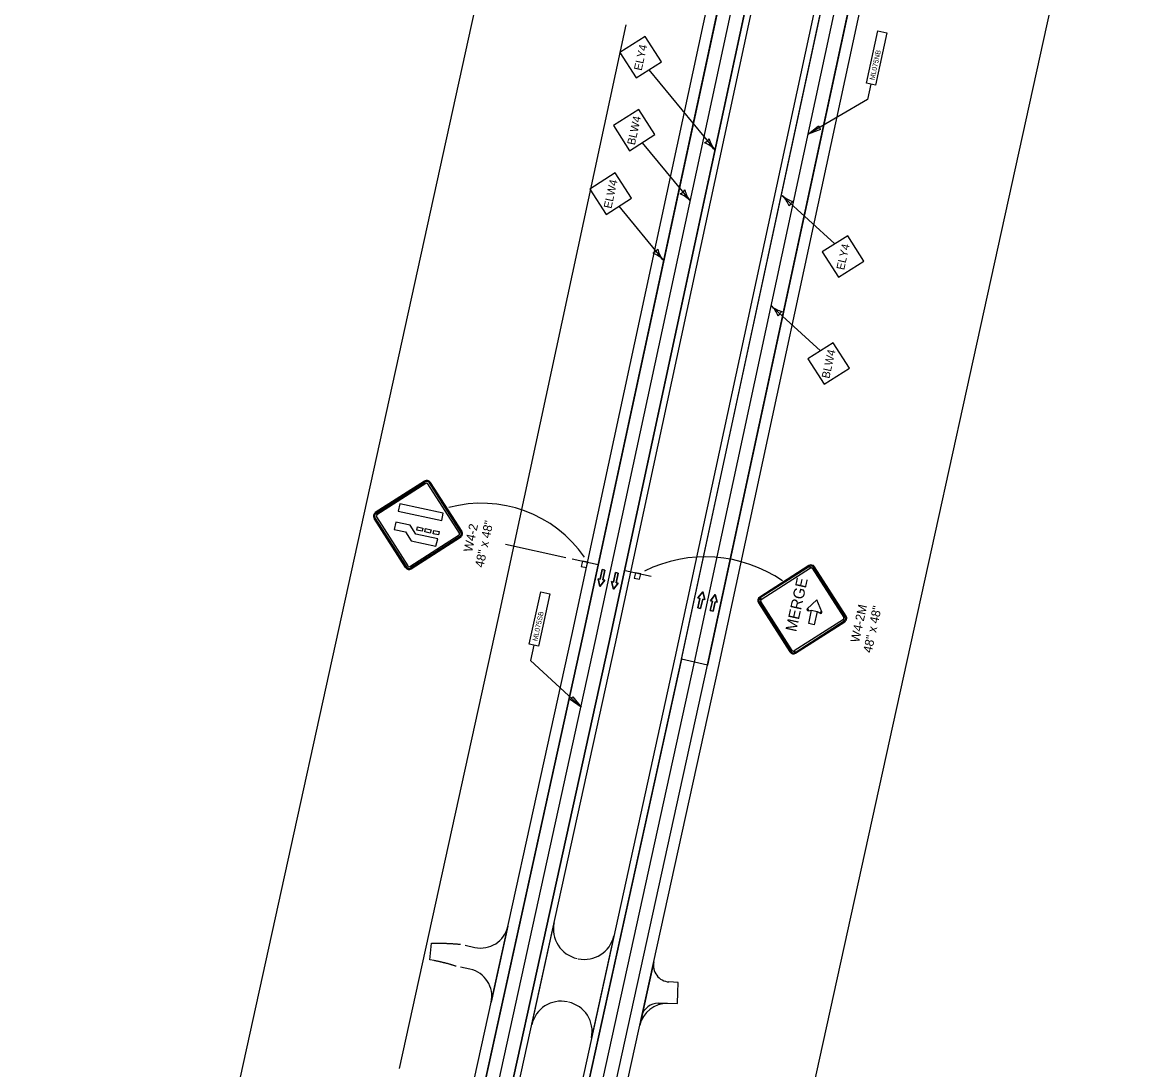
# Model space of a CAD drawing. Extents: x 14104283 to 14120882, y 8635219 to 8671666.
# Drawn here: x 14108108 to 14109111, y 8642822 to 8643764 of the extents above; entities that cross this region are included whole.
import ezdxf

# ---------------------------------------------------------------- set-up
doc = ezdxf.new("R2010")
doc.units = 0
for name, color, linetype in [('Cell', 7, 'Continuous'), ('dsnNonPlotable', 7, 'Continuous'), ('dsnPaintExistingEdgeLineRightWhite', 7, 'Continuous'), ('dsnPaintPlaceBrokenLineWhite', 7, 'Continuous'), ('dsnPaintPlaceEdgeLineLeftYellow', 7, 'Continuous'), ('dsnPaintPlaceEdgeLineRightWhite', 7, 'Continuous'), ('dsnPaintRemoveDoubleCenterLineYellow', 7, 'Continuous'), ('dsnShadingPaved', 7, 'Continuous'), ('dsnStdLabel', 7, 'Continuous'), ('dsnStgShadingPrevPav', 7, 'Continuous'), ('Text', 7, 'Continuous')]:
    doc.layers.add(name, color=color, linetype=linetype)

msp = doc.modelspace()

# ---------------------------------------------------------------- linework, layer by layer
at = {"layer": 'Cell'}
for p, q in [((14108425.2, 8643322.8), (14108469.5, 8643351.1)), ((14108469.5, 8643351.1), (14108425.2, 8643322.8)), ((14108425.7, 8643322), (14108470, 8643350.3)), ((14108470.8, 8643349), (14108426.6, 8643320.7)), ((14108500.8, 8643304.4), (14108472.5, 8643348.6)), ((14108473.9, 8643349.5), (14108502.1, 8643305.2)), ((14108474.6, 8643350), (14108502.9, 8643305.8)), ((14108502.9, 8643305.8), (14108474.6, 8643350)), ((14108452.4, 8643273.4), (14108424.1, 8643317.6)), ((14108424.1, 8643317.6), (14108452.4, 8643273.4)), ((14108424.1, 8643317.6), (14108424.1, 8643317.6)), ((14108453.2, 8643273.9), (14108424.9, 8643318.1)), ((14108426.2, 8643319), (14108426.2, 8643319)), ((14108426.2, 8643319), (14108454.5, 8643274.8)), ((14108456.2, 8643274.4), (14108500.5, 8643302.7)), ((14108501.3, 8643301.4), (14108457.1, 8643273.1)), ((14108501.8, 8643300.6), (14108457.6, 8643272.3)), ((14108457.6, 8643272.3), (14108501.8, 8643300.6)), ((14108602.2, 8643281.2), (14108625.7, 8643276.1)), ((14108815.1, 8643275.2), (14108770.9, 8643246.9)), ((14108815.6, 8643274.4), (14108816.5, 8643273.1)), ((14108818.2, 8643272.7), (14108819.5, 8643273.5)), ((14108848.6, 8643229.8), (14108820.3, 8643274)), ((14108649.9, 8643270.7), (14108673.3, 8643265.6)), ((14108770.5, 8643242.2), (14108771.9, 8643243)), ((14108772.2, 8643244.8), (14108771.4, 8643246.1)), ((14108769.7, 8643241.7), (14108798, 8643197.5)), ((14108814.4, 8643235.6), (14108813.7, 8643236.4)), ((14108814.5, 8643234.6), (14108814.4, 8643235.6)), ((14108825.7, 8643233.2), (14108825.2, 8643232.3)), ((14108826.7, 8643233.5), (14108825.7, 8643233.2)), ((14108803.2, 8643196.3), (14108847.4, 8643224.6)), ((14108846.1, 8643226.7), (14108846.9, 8643225.4)), ((14108847.8, 8643229.3), (14108846.5, 8643228.5)), ((14108800.1, 8643198.8), (14108798.8, 8643198)), ((14108802.7, 8643197.1), (14108801.9, 8643198.4))]:
    msp.add_line(p, q, dxfattribs=at)
for points in [[(14108470, 8643350.3), (14108425.7, 8643322)], [(14108470.8, 8643349), (14108426.6, 8643320.7)], [(14108500.8, 8643304.4), (14108472.5, 8643348.6)], [(14108502.1, 8643305.2), (14108473.9, 8643349.5)], [(14108424.9, 8643318.1), (14108453.2, 8643273.9)], [(14108426.2, 8643319), (14108454.5, 8643274.8)], [(14108456.2, 8643274.4), (14108500.5, 8643302.7)], [(14108457.1, 8643273.1), (14108501.3, 8643301.4)], [(14108616.2, 8643278.1), (14108611.4, 8643279.1), (14108610.4, 8643274.3), (14108615.2, 8643273.3), (14108616.2, 8643278.1)], [(14108627.3, 8643262.9), (14108625.5, 8643263.3), (14108627.2, 8643256.5), (14108631.6, 8643262), (14108629.8, 8643262.4), (14108631.6, 8643270.9), (14108629.2, 8643271.5), (14108627.3, 8643262.9)], [(14108639.4, 8643260.3), (14108637.6, 8643260.7), (14108639.3, 8643253.9), (14108643.7, 8643259.3), (14108641.8, 8643259.7), (14108643.7, 8643268.3), (14108641.3, 8643268.8), (14108639.4, 8643260.3)], [(14108663.9, 8643267.6), (14108659.1, 8643268.6), (14108658.1, 8643263.8), (14108662.9, 8643262.8), (14108663.9, 8643267.6)], [(14108719.6, 8643245.1), (14108721.5, 8643244.7), (14108719.7, 8643251.5), (14108715.4, 8643246.1), (14108717.2, 8643245.7), (14108715.3, 8643237.1), (14108717.8, 8643236.6), (14108719.6, 8643245.1)], [(14108719.6, 8643245.1), (14108721.5, 8643244.7), (14108719.7, 8643251.5), (14108715.4, 8643246.1), (14108717.2, 8643245.7), (14108715.3, 8643237.1), (14108717.8, 8643236.6), (14108719.6, 8643245.1)], [(14108730.7, 8643242.7), (14108732.6, 8643242.3), (14108730.8, 8643249.1), (14108726.5, 8643243.6), (14108728.3, 8643243.2), (14108726.4, 8643234.7), (14108728.9, 8643234.1), (14108730.7, 8643242.7)]]:
    msp.add_lwpolyline(points, dxfattribs=at)
for points in [[(14108445.8, 8643324.2), (14108484.9, 8643315.6), (14108486.3, 8643322.2), (14108447.2, 8643330.8)], [(14108452.5, 8643305.4), (14108457.5, 8643297.5), (14108479.8, 8643292.6), (14108481.3, 8643299.2), (14108461.7, 8643303.5), (14108456.7, 8643311.4), (14108443.6, 8643314.3), (14108442.2, 8643307.7)], [(14108462.5, 8643307.1), (14108463.1, 8643310), (14108468, 8643308.9), (14108467.4, 8643306)], [(14108469.8, 8643305.4), (14108470.5, 8643308.4), (14108475.4, 8643307.3), (14108474.7, 8643304.4)], [(14108477.2, 8643303.8), (14108477.8, 8643306.8), (14108482.7, 8643305.7), (14108482, 8643302.8)], [(14108616.2, 8643278.1), (14108611.4, 8643279.1), (14108610.4, 8643274.3), (14108615.2, 8643273.3)], [(14108815.6, 8643274.4), (14108771.4, 8643246.1), (14108772.2, 8643244.8), (14108816.5, 8643273.1), (14108815.6, 8643274.4)], [(14108847.8, 8643229.3), (14108819.5, 8643273.5), (14108818.2, 8643272.7), (14108846.5, 8643228.5), (14108847.8, 8643229.3)], [(14108629.2, 8643271.5), (14108631.6, 8643270.9), (14108629.8, 8643262.4), (14108631.6, 8643262), (14108627.2, 8643256.5), (14108625.5, 8643263.3), (14108627.3, 8643262.9)], [(14108641.3, 8643268.8), (14108643.7, 8643268.3), (14108641.8, 8643259.7), (14108643.7, 8643259.3), (14108639.3, 8643253.9), (14108637.6, 8643260.7), (14108639.4, 8643260.3)], [(14108663.9, 8643267.6), (14108659.1, 8643268.6), (14108658.1, 8643263.8), (14108662.9, 8643262.8)], [(14108717.8, 8643236.6), (14108715.3, 8643237.1), (14108717.2, 8643245.7), (14108715.4, 8643246.1), (14108719.7, 8643251.5), (14108721.5, 8643244.7), (14108719.6, 8643245.1)], [(14108717.8, 8643236.6), (14108715.3, 8643237.1), (14108717.2, 8643245.7), (14108715.4, 8643246.1), (14108719.7, 8643251.5), (14108721.5, 8643244.7), (14108719.6, 8643245.1)], [(14108728.9, 8643234.1), (14108726.4, 8643234.7), (14108728.3, 8643243.2), (14108726.5, 8643243.6), (14108730.8, 8643249.1), (14108732.6, 8643242.3), (14108730.7, 8643242.7)], [(14108770.5, 8643242.2), (14108798.8, 8643198), (14108800.1, 8643198.8), (14108771.9, 8643243), (14108770.5, 8643242.2)], [(14108822.2, 8643244.3), (14108813.7, 8643236.4), (14108814.4, 8643235.6), (14108814.5, 8643234.6), (14108817.6, 8643235), (14108822.5, 8643233.9), (14108825.2, 8643232.3), (14108825.7, 8643233.2), (14108826.7, 8643233.5), (14108822.2, 8643244.3)], [(14108819.9, 8643222), (14108815, 8643223), (14108817.6, 8643235), (14108822.5, 8643233.9), (14108819.9, 8643222)], [(14108802.7, 8643197.1), (14108846.9, 8643225.4), (14108846.1, 8643226.7), (14108801.9, 8643198.4), (14108802.7, 8643197.1)]]:
    msp.add_lwpolyline(points, close=True, dxfattribs=at)
for centre, radius, start, end in [((14108471.5, 8643348), 3.75, 32.6079, 122.6081), ((14108471.5, 8643348), 3.75, 32.6079, 122.6081), ((14108471.5, 8643348), 2.81, 32.6079, 122.6081), ((14108471.5, 8643348), 2.81, 32.6079, 122.6081), ((14108471.5, 8643348), 1.25, 32.6079, 122.6081), ((14108471.5, 8643348), 1.25, 32.6079, 122.6081), ((14108427.3, 8643319.7), 3.75, 122.6081, 212.6078), ((14108427.3, 8643319.7), 3.75, 122.6081, 212.6078), ((14108427.3, 8643319.7), 2.81, 122.6081, 212.6078), ((14108427.3, 8643319.7), 2.81, 122.6081, 212.6078), ((14108427.3, 8643319.7), 1.25, 122.6081, 212.6078), ((14108427.3, 8643319.7), 1.25, 122.6081, 212.6078), ((14108499.8, 8643303.7), 1.25, 302.6077, 32.6079), ((14108499.8, 8643303.7), 1.25, 302.6077, 32.6079), ((14108499.8, 8643303.7), 2.81, 302.6077, 32.6079), ((14108499.8, 8643303.7), 2.81, 302.6077, 32.6079), ((14108499.8, 8643303.7), 3.75, 302.6077, 32.6079), ((14108499.8, 8643303.7), 3.75, 302.6077, 32.6079), ((14108455.6, 8643275.4), 3.75, 212.608, 302.6077), ((14108455.6, 8643275.4), 3.75, 212.608, 302.6077), ((14108455.6, 8643275.4), 2.81, 212.608, 302.6077), ((14108455.6, 8643275.4), 2.81, 212.608, 302.6077), ((14108455.6, 8643275.4), 1.25, 212.608, 302.6077), ((14108455.6, 8643275.4), 1.25, 212.608, 302.6077), ((14108817.1, 8643272), 3.75, 32.608, 122.6076), ((14108817.1, 8643272), 2.81, 32.608, 122.6076), ((14108817.1, 8643272), 1.25, 32.608, 122.6076), ((14108772.9, 8643243.7), 3.75, 122.6078, 212.6076), ((14108772.9, 8643243.7), 2.81, 122.6078, 212.6076), ((14108772.9, 8643243.7), 1.25, 122.6078, 212.6076), ((14108814.4, 8643235.6), 1.02, 135.2955, 276.1893), ((14108825.7, 8643233.2), 1.02, 239.0261, 19.9204), ((14108845.4, 8643227.8), 1.25, 302.6078, 32.608), ((14108845.4, 8643227.8), 2.81, 302.6078, 32.608), ((14108845.4, 8643227.8), 3.75, 302.6078, 32.608), ((14108801.2, 8643199.5), 3.75, 212.6076, 302.6078), ((14108801.2, 8643199.5), 2.81, 212.6076, 302.6078), ((14108801.2, 8643199.5), 1.25, 212.6076, 302.6078)]:
    msp.add_arc(centre, radius, start, end, dxfattribs=at)
at = {"layer": 'dsnNonPlotable'}
msp.add_lwpolyline([(14108281.2, 8642711.6), (14108617.6, 8644242.5), (14109110.8, 8644134.2), (14108774.4, 8642603.2)], close=True, dxfattribs=at)
at = {"layer": 'dsnPaintExistingEdgeLineRightWhite'}
for p, q in [((14108724, 8643185.8), (14109088.7, 8644879.7)), ((14108201.6, 8640807.6), (14108724, 8643185.7))]:
    msp.add_line(p, q, dxfattribs=at)
at = {"layer": 'dsnPaintPlaceBrokenLineWhite'}
for p, q in [((14108623.3, 8643207.7), (14108988, 8644901.3)), ((14108423.2, 8642296.7), (14108623.3, 8643207.7))]:
    msp.add_line(p, q, dxfattribs=at)
msp.add_lwpolyline([(14108306.4, 8641340.7), (14108389, 8641717), (14108712.3, 8643188.3), (14108894.6, 8644035.3), (14109077, 8644882.2)], dxfattribs=at)
at = {"layer": 'dsnPaintPlaceEdgeLineLeftYellow'}
for p, q in [((14108700.5, 8643190.8), (14109065.3, 8644884.7)), ((14108199.6, 8640910.3), (14108700.5, 8643190.8))]:
    msp.add_line(p, q, dxfattribs=at)
msp.add_lwpolyline([(14108999.8, 8644898.8), (14108635.1, 8643205.1), (14108434.9, 8642294.1)], dxfattribs=at)
at = {"layer": 'dsnPaintPlaceEdgeLineRightWhite'}
msp.add_lwpolyline([(14108976.3, 8644903.9), (14108611.6, 8643210.2), (14108202.1, 8641346.1)], dxfattribs=at)
at = {"layer": 'dsnPaintRemoveDoubleCenterLineYellow'}
msp.add_lwpolyline([(14108306.4, 8641340.7), (14108389, 8641717), (14108712.3, 8643188.3), (14108894.6, 8644035.3), (14109077, 8644882.2)], dxfattribs=at)
at = {"layer": 'dsnShadingPaved'}
for p, q in [((14108700.5, 8643190.9), (14108199.6, 8640910.3)), ((14108201.6, 8640807.6), (14108724, 8643185.7)), ((14108724, 8643185.7), (14108700.5, 8643190.9))]:
    msp.add_line(p, q, dxfattribs=at)
for points in [[(14108976.3, 8644903.9), (14108611.6, 8643210.2), (14108202.1, 8641346.1)], [(14108434.9, 8642294.1), (14108635.1, 8643205.1), (14108999.8, 8644898.8)]]:
    msp.add_lwpolyline(points, dxfattribs=at)
msp.add_lwpolyline([(14109065.3, 8644884.7), (14109088.7, 8644879.7), (14108724, 8643185.7), (14108700.5, 8643190.9)], close=True, dxfattribs=at)
at = {"layer": 'dsnStdLabel'}
for p, q in [((14108671.1, 8643720.9), (14108730.5, 8643649)), ((14108665.3, 8643655.3), (14108708.4, 8643603)), ((14108838.6, 8643564.4), (14108791.2, 8643607.7)), ((14108644.1, 8643598.2), (14108684.1, 8643549.8)), ((14108825.6, 8643468.2), (14108781.3, 8643508.8)), ((14108542.4, 8643294.4), (14108596.5, 8643282.5))]:
    msp.add_line(p, q, dxfattribs=at)
msp.add_lwpolyline([(14108650.5, 8643761.2), (14108535.4, 8643226.8), (14108446.7, 8642823.1)], dxfattribs=at)
for points in [[(14108659.7, 8643713.6), (14108682.5, 8643728.2), (14108667.9, 8643750.9), (14108645.2, 8643736.4)], [(14108653.9, 8643648), (14108676.6, 8643662.6), (14108662.1, 8643685.3), (14108639.3, 8643670.8)], [(14108632.8, 8643590.9), (14108655.5, 8643605.5), (14108641, 8643628.2), (14108618.2, 8643613.7)], [(14108841.8, 8643534.4), (14108864.5, 8643548.9), (14108850, 8643571.7), (14108827.2, 8643557.1)], [(14108828.8, 8643438.2), (14108851.5, 8643452.7), (14108837, 8643475.5), (14108814.2, 8643460.9)]]:
    msp.add_lwpolyline(points, close=True, dxfattribs=at)
for centre, radius, start, end in [((14108718, 8643663.6), 8.86, 292.8385, 328.307), ((14108713, 8643634), 22.9, 40.5727, 68.6439), ((14108747.9, 8643663.9), 22.9, 192.5015, 220.5728), ((14108695.9, 8643617.6), 8.86, 292.8385, 328.307), ((14108691, 8643588.1), 22.9, 40.5727, 68.6439), ((14108725.9, 8643617.9), 22.9, 192.5015, 220.5728), ((14108775.7, 8643590.8), 22.9, 19.4977, 47.569), ((14108806.7, 8643624.7), 22.9, 227.5689, 255.6401), ((14108805.4, 8643594.7), 8.86, 119.8347, 155.3031), ((14108671.6, 8643564.4), 8.86, 292.8385, 328.307), ((14108666.7, 8643534.8), 22.9, 40.5727, 68.6439), ((14108701.5, 8643564.7), 22.9, 192.5015, 220.5728), ((14108765.8, 8643491.8), 22.9, 19.4977, 47.569), ((14108796.7, 8643525.7), 22.9, 227.5689, 255.6401), ((14108795.5, 8643495.8), 8.86, 119.8347, 155.3031), ((14108520.9, 8643218.9), 112.3, 34.5988, 105.2065), ((14108721.8, 8643160.3), 122.7, 55.4671, 116.4111)]:
    msp.add_arc(centre, radius, start, end, dxfattribs=at)
at = {"layer": 'dsnStgShadingPrevPav'}
for p, q in [((14108601.8, 8643212.3), (14108966.5, 8644906)), ((14108976.3, 8644903.9), (14108611.6, 8643210.2)), ((14109059.4, 8644886), (14108694.7, 8643192.1)), ((14108733.8, 8643183.6), (14109098.5, 8644877.6)), ((14108107.8, 8640963.3), (14108601.8, 8643212.3)), ((14108611.6, 8643210.2), (14108117.6, 8640961.2)), ((14108694.7, 8643192.1), (14108383, 8641773.2)), ((14108422, 8641764.6), (14108733.8, 8643183.6)), ((14108565.9, 8642862.3), (14108586.1, 8642954.1)), ((14108544.4, 8642950.9), (14108529.4, 8642882.6)), ((14108639.8, 8642942.3), (14108619.6, 8642850.5)), ((14108474.4, 8642920.7), (14108475.7, 8642935.7)), ((14108475.7, 8642935.7), (14108479.6, 8642935.7)), ((14108506.1, 8642933.8), (14108514.6, 8642931.9)), ((14108478.2, 8642920), (14108474.4, 8642920.7)), ((14108510.3, 8642912.3), (14108501.8, 8642914.2)), ((14108675.6, 8642919), (14108669.7, 8642892)), ((14108669.7, 8642892), (14108664.8, 8642869.9)), ((14108697.5, 8642900.3), (14108689.2, 8642900.9)), ((14108697, 8642881.3), (14108697.3, 8642891.3)), ((14108697.3, 8642891.3), (14108697.5, 8642900.3)), ((14108679.9, 8642881.7), (14108697, 8642881.3)), ((14108688.1, 8642881.5), (14108679.9, 8642881.7)), ((14108664.8, 8642869.9), (14108663.1, 8642861.9))]:
    msp.add_line(p, q, dxfattribs=at)
for points in [[(14108999.8, 8644898.8), (14108817.4, 8644052), (14108635.1, 8643205.1), (14108387.9, 8642080.1), (14108140.8, 8640955.1)], [(14108146.7, 8640953.8), (14108640.9, 8643203.9), (14109005.6, 8644897.6)], [(14108202.1, 8641346.1), (14108611.6, 8643210.2), (14108976.3, 8644903.9)], [(14108999.8, 8644898.8), (14108635.1, 8643205.1), (14108225.5, 8641340.9)]]:
    msp.add_lwpolyline(points, dxfattribs=at)
for centre, radius, start, end in [((14108612.4, 8642948.3), 27, 167.6102, 257.6102), ((14108520, 8642956.3), 25, 257.6102, 347.6102), ((14108613.4, 8642948.1), 27, 257.6102, 347.6102), ((14108505, 8642887.9), 25, 347.6102, 77.6102), ((14108690.3, 8642915.8), 15, 167.6102, 266.0309), ((14108592.3, 8642856.5), 27, 77.6102, 167.6102), ((14108593.2, 8642856.3), 27, 347.6102, 77.6102), ((14108687.5, 8642856.5), 25, 88.6111, 167.6102), ((14108679.5, 8642866.7), 15, 88.6102, 167.6102), ((14108679.5, 8642866.7), 15, 88.6102, 167.6102)]:
    msp.add_arc(centre, radius, start, end, dxfattribs=at)
for points in [[(14108479.6, 8642935.7), (14108480, 8642935.7), (14108480.7, 8642935.7), (14108481.8, 8642935.7), (14108482.9, 8642935.7), (14108484, 8642935.7), (14108485.1, 8642935.7), (14108486.2, 8642935.6), (14108487.3, 8642935.6), (14108488.4, 8642935.6), (14108489.5, 8642935.5), (14108490.6, 8642935.5), (14108491.8, 8642935.4), (14108492.9, 8642935.4), (14108494, 8642935.3), (14108495.1, 8642935.2), (14108496.2, 8642935.2), (14108497.3, 8642935.1), (14108498.4, 8642935), (14108499.5, 8642934.9), (14108500.6, 8642934.8), (14108501.4, 8642934.7), (14108501.7, 8642934.7)], [(14108497.8, 8642915), (14108497.5, 8642915.1), (14108496.9, 8642915.3), (14108495.9, 8642915.6), (14108494.9, 8642915.9), (14108494, 8642916.2), (14108493, 8642916.5), (14108492, 8642916.7), (14108491.1, 8642917), (14108490.1, 8642917.3), (14108489.1, 8642917.5), (14108488.1, 8642917.8), (14108487.1, 8642918), (14108486.1, 8642918.3), (14108485.1, 8642918.5), (14108484.2, 8642918.7), (14108483.2, 8642919), (14108482.2, 8642919.2), (14108481.2, 8642919.4), (14108480.2, 8642919.6), (14108479.2, 8642919.8), (14108478.5, 8642919.9), (14108478.2, 8642920)]]:
    msp.add_open_spline(points, degree=3, dxfattribs=at)
at = {"layer": 'Text'}
for points in [[(14108866.8, 8643709), (14108877.1, 8643756), (14108885.3, 8643754.2), (14108875, 8643707.2)], [(14108866.8, 8643709), (14108877.1, 8643756), (14108885.3, 8643754.2), (14108875, 8643707.2)], [(14108814.4, 8643662.9), (14108823.7, 8643670.4), (14108825.5, 8643667.3)], [(14108563.7, 8643204.6), (14108574.1, 8643251.6), (14108582.3, 8643249.8), (14108571.9, 8643202.8)], [(14108563.7, 8643204.6), (14108574.1, 8643251.6), (14108582.3, 8643249.8), (14108571.9, 8643202.8)], [(14108610.2, 8643148), (14108600.3, 8643154.7), (14108602.7, 8643157.3)]]:
    msp.add_lwpolyline(points, close=True, dxfattribs=at)
for points in [[(14108870.9, 8643708.1), (14108867.7, 8643694.1), (14108814.4, 8643662.9)], [(14108567.8, 8643203.7), (14108564.7, 8643189.7), (14108610.2, 8643148)]]:
    msp.add_lwpolyline(points, dxfattribs=at)

# ---------------------------------------------------------------- texts
at = {"layer": 'Cell'}
for s, height, p in [('W4-2', 8, (14108512.2, 8643286.8)), ('48" x 48"', 8, (14108522.4, 8643272.9)), ('MERGE', 10, (14108803.7, 8643215.1)), ('W4-2M', 8, (14108860.2, 8643205.5)), ('48" x 48"', 8, (14108871.5, 8643196.2))]:
    msp.add_text(s, height=height, rotation=77.6078, dxfattribs=at).set_placement(p)
at = {"layer": 'dsnStdLabel'}
for s, p in [('ELY4', (14108664.7, 8643719.7)), ('BLW4', (14108658.6, 8643652.8)), ('ELW4', (14108637.5, 8643595.7)), ('ELY4', (14108846.8, 8643540.5)), ('BLW4', (14108833.5, 8643442.9))]:
    msp.add_text(s, height=7.2, rotation=77.6078, dxfattribs=at).set_placement(p)
at = {"layer": 'Text'}
for s, p in [('ML075NB', (14108874, 8643711.3)), ('ML075SB', (14108570.9, 8643206.9))]:
    msp.add_text(s, height=4.48, rotation=77.6078, dxfattribs=at).set_placement(p)

doc.saveas('drawing.dxf')
